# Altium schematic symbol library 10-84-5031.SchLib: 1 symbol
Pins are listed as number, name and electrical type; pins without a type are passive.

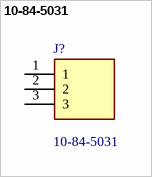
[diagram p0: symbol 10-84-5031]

## 10-84-5031
designator J?
Pin & Socket Connectors; Manufacturer_Name: Molex; Geometry.Height: 13.97mm
footprint SHDR3W166P0X635_1X3_2032X762X1397P
pins: 1, 2, 3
